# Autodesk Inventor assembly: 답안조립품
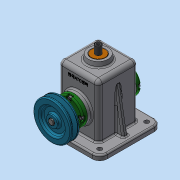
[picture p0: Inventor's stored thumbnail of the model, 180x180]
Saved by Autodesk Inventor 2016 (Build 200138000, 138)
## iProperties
Created: 2022-11
Part Number: 답안조립품
Material: 일반
Document SubType Name: Assembly
Designer: 하동건
Author: 하동건
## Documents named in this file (15)
- C:\Users\CAD06\Downloads\721106V1008\답안조립품.iam
- C:\Users\CAD06\Downloads\721106V1008\본체.ipt
- C:\Users\CAD06\Downloads\721106V1008\편심축.ipt
- C:\Users\CAD06\Downloads\721106V1008\뒤커버.ipt
- C:\Users\CAD06\Downloads\721106V1008\볼트 M4 x 12.ipt
- C:\Users\CAD06\Downloads\721106V1008\베어링 6201.ipt
- C:\Users\CAD06\Downloads\721106V1008\앞커버.ipt
- C:\Users\CAD06\Downloads\721106V1008\부시.ipt
- C:\Users\CAD06\Downloads\721106V1008\슬라이드.ipt
- C:\Users\CAD06\Downloads\721106V1008\링크.ipt
- C:\Users\CAD06\Downloads\721106V1008\핀 5 x 18.ipt
- C:\Users\CAD06\Downloads\721106V1008\고정핀 1.2 x 10.ipt
- C:\Users\CAD06\Downloads\721106V1008\키 4 x 4 x 15.ipt
- C:\Users\CAD06\Downloads\721106V1008\V벨트풀리.ipt
- C:\Users\CAD06\Downloads\721106V1008\멈춤나사 M3 x 8.ipt
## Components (11 placed, 4 different names)
1. 핀 5 x 18:1
2. 고정핀 1.2 x 10:1
3. V벨트풀리:1
4. ISO 4762 M4 x 12:2
5. ISO 4762 M4 x 12:3
6. ISO 4762 M4 x 12:4
7. ISO 4762 M4 x 12:5
8. ISO 4762 M4 x 12:1
9. ISO 4762 M4 x 12:6
10. ISO 4762 M4 x 12:7
11. ISO 4762 M4 x 12:8
